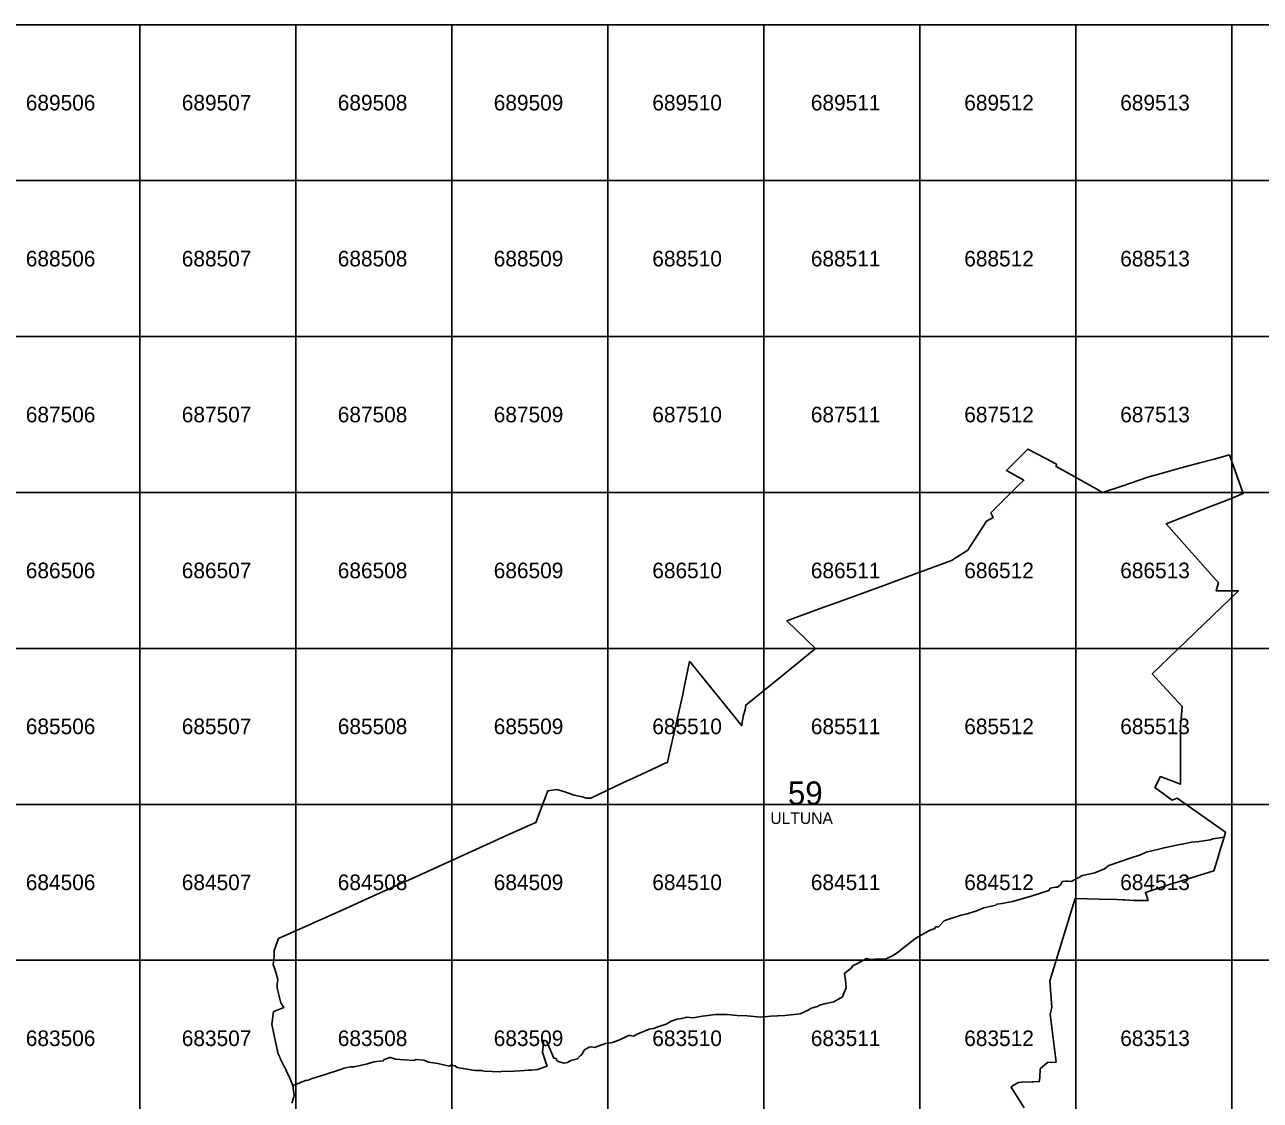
# Model space of a CAD drawing. Extents: x 25485000 to 25520000, y 6656775 to 6690000.
# Drawn here: x 25506262 to 25514183, y 6683102 to 6690000 of the extents above; entities that cross this region are included whole.
import ezdxf

# ---------------------------------------------------------------- set-up
doc = ezdxf.new("R2010")
doc.units = 0
doc.layers.add('Level 63', color=7, linetype='Continuous')

msp = doc.modelspace()

# ---------------------------------------------------------------- linework, layer by layer
at = {"layer": 'Level 63'}
for points in [[(25506000, 6689000), (25507000, 6689000), (25507000, 6690000), (25506000, 6690000)], [(25507000, 6689000), (25508000, 6689000), (25508000, 6690000), (25507000, 6690000)], [(25508000, 6689000), (25509000, 6689000), (25509000, 6690000), (25508000, 6690000)], [(25509000, 6689000), (25510000, 6689000), (25510000, 6690000), (25509000, 6690000)], [(25510000, 6689000), (25511000, 6689000), (25511000, 6690000), (25510000, 6690000)], [(25511000, 6689000), (25512000, 6689000), (25512000, 6690000), (25511000, 6690000)], [(25512000, 6689000), (25513000, 6689000), (25513000, 6690000), (25512000, 6690000)], [(25513000, 6689000), (25514000, 6689000), (25514000, 6690000), (25513000, 6690000)], [(25514000, 6689000), (25515000, 6689000), (25515000, 6690000), (25514000, 6690000)], [(25506000, 6688000), (25507000, 6688000), (25507000, 6689000), (25506000, 6689000)], [(25507000, 6688000), (25508000, 6688000), (25508000, 6689000), (25507000, 6689000)], [(25508000, 6688000), (25509000, 6688000), (25509000, 6689000), (25508000, 6689000)], [(25509000, 6688000), (25510000, 6688000), (25510000, 6689000), (25509000, 6689000)], [(25510000, 6688000), (25511000, 6688000), (25511000, 6689000), (25510000, 6689000)], [(25511000, 6688000), (25512000, 6688000), (25512000, 6689000), (25511000, 6689000)], [(25512000, 6688000), (25513000, 6688000), (25513000, 6689000), (25512000, 6689000)], [(25513000, 6688000), (25514000, 6688000), (25514000, 6689000), (25513000, 6689000)], [(25514000, 6688000), (25515000, 6688000), (25515000, 6689000), (25514000, 6689000)], [(25506000, 6687000), (25507000, 6687000), (25507000, 6688000), (25506000, 6688000)], [(25507000, 6687000), (25508000, 6687000), (25508000, 6688000), (25507000, 6688000)], [(25508000, 6687000), (25509000, 6687000), (25509000, 6688000), (25508000, 6688000)], [(25509000, 6687000), (25510000, 6687000), (25510000, 6688000), (25509000, 6688000)], [(25510000, 6687000), (25511000, 6687000), (25511000, 6688000), (25510000, 6688000)], [(25511000, 6687000), (25512000, 6687000), (25512000, 6688000), (25511000, 6688000)], [(25512000, 6687000), (25513000, 6687000), (25513000, 6688000), (25512000, 6688000)], [(25513000, 6687000), (25514000, 6687000), (25514000, 6688000), (25513000, 6688000)], [(25514000, 6687000), (25515000, 6687000), (25515000, 6688000), (25514000, 6688000)], [(25507847.3, 6683582.4), (25507847.8, 6683580), (25507869.5, 6683475.9), (25507881.4, 6683418.8), (25507882, 6683416.3), (25507882.2, 6683415.6), (25507883.4, 6683411.3), (25507883.5, 6683411), (25507885.2, 6683405.4), (25507886.6, 6683401.2), (25507889, 6683394.1), (25507890, 6683392), (25507895.7, 6683384.5), (25507897.7, 6683376.6), (25507899.4, 6683372.8), (25507900.8, 6683369.4), (25507902.2, 6683366.1), (25507903.7, 6683362.5), (25507905.7, 6683357.8), (25507910, 6683347.6), (25507915.8, 6683336.1), (25507924.8, 6683319.1), (25507930.5, 6683307.5), (25507934.9, 6683298.6), (25507940.6, 6683286.9), (25507949.9, 6683268.2), (25507967.5, 6683229), (25507975.8, 6683208.3), (25507979.5, 6683195.8), (25507984.3, 6683197.2), (25508065.8, 6683230), (25508073.3, 6683229.8), (25508103.9, 6683242.5), (25508180.9, 6683266.1), (25508287.1, 6683299.7), (25508309.5, 6683308), (25508349.1, 6683316.9), (25508373.2, 6683315.9), (25508458.2, 6683335.5), (25508460.1, 6683335.9), (25508501.3, 6683349), (25508517.7, 6683350.9), (25508560.2, 6683354), (25508565, 6683364.6), (25508603, 6683375.9), (25508606.4, 6683376.9), (25508638, 6683365.9), (25508755.1, 6683358), (25508772, 6683363.4), (25508819.6, 6683358.6), (25508851.2, 6683346.3), (25508910.4, 6683337), (25508983.1, 6683321.2), (25508995.7, 6683327.7), (25509020.3, 6683323.5), (25509034.8, 6683312.7), (25509150.2, 6683292.8), (25509189.6, 6683293.6), (25509207.4, 6683287.8), (25509305.6, 6683283.5), (25509327.6, 6683289.6), (25509366.6, 6683287.6), (25509466.4, 6683293.7), (25509487.9, 6683295), (25509513.6, 6683295.5), (25509549.1, 6683300.5), (25509610.1, 6683319.9), (25509600.7, 6683349.8), (25509580.5, 6683411.1), (25509590.6, 6683486.9), (25509606.7, 6683483.2), (25509653.4, 6683371.6), (25509668, 6683370.5), (25509673.7, 6683357.5), (25509687.4, 6683347.6), (25509720.6, 6683340.8), (25509741.5, 6683345), (25509762.9, 6683357.9), (25509806.6, 6683366.8), (25509823.5, 6683386.5), (25509832.3, 6683396.1), (25509848.6, 6683422.7), (25509851, 6683426.6), (25509880.1, 6683442.2), (25509894.7, 6683445.5), (25509916.7, 6683441.2), (25509941.5, 6683451), (25509955.2, 6683454.6), (25509984.6, 6683465.8), (25510030.7, 6683471.7), (25510082.1, 6683491.8), (25510133.3, 6683518.3), (25510143.6, 6683517.4), (25510164.4, 6683514.2), (25510184.4, 6683524.2), (25510202.1, 6683532.1), (25510265.1, 6683558.7), (25510293, 6683561.4), (25510326.2, 6683576.1), (25510373.7, 6683589.2), (25510406.4, 6683609.6), (25510444, 6683622.6), (25510471.5, 6683626.8), (25510481.2, 6683628.2), (25510505.5, 6683636.1), (25510546.8, 6683630.7), (25510606.8, 6683641.6), (25510689.7, 6683651.7), (25510764.6, 6683652.6), (25510828.2, 6683645.5), (25510894.2, 6683642.9), (25510981.1, 6683636.1), (25511044.2, 6683640.9), (25511134.6, 6683645.8), (25511233.3, 6683656.8), (25511284.7, 6683679.2), (25511304.1, 6683693.8), (25511343.4, 6683702.5), (25511357.1, 6683713.1), (25511396.9, 6683723.8), (25511448.8, 6683734.2), (25511504, 6683765.6), (25511513.2, 6683789), (25511527.1, 6683822.7), (25511523.5, 6683872.2), (25511517, 6683915.9), (25511542, 6683936.2), (25511562.4, 6683951.3), (25511569.2, 6683963.2), (25511569, 6683963.7), (25511592.9, 6683974.4), (25511658.2, 6684010.3), (25511686.7, 6684005.2), (25511731.5, 6684009), (25511777.5, 6684007.9), (25511821.6, 6684025.4), (25511854.5, 6684048.2), (25511957.6, 6684129.6), (25511979.4, 6684142.9), (25512053.1, 6684187.2), (25512069.8, 6684195), (25512079.8, 6684197.3), (25512095.8, 6684204.1), (25512101, 6684214.1), (25512119.9, 6684214.9), (25512157.3, 6684253), (25512167.3, 6684256.3), (25512264.3, 6684288.6), (25512294.8, 6684296.4), (25512359.1, 6684314.4), (25512410.8, 6684337.2), (25512487.2, 6684352.8), (25512493.1, 6684360.4), (25512527, 6684363.9), (25512594, 6684376.7), (25512708.6, 6684408.2), (25512827.1, 6684446.4), (25512836.4, 6684461.4), (25512869.1, 6684468), (25512883.3, 6684469.3), (25512901.4, 6684484.6), (25512913.5, 6684505.6), (25512934.3, 6684506.8), (25512951.5, 6684507.9), (25512970.1, 6684504.8), (25513043.6, 6684544.3), (25513122.5, 6684561), (25513183.3, 6684586.9), (25513212.6, 6684608), (25513348.2, 6684655.2), (25513414.4, 6684675.7), (25513451.6, 6684694.1), (25513525, 6684710.5), (25513566.1, 6684721.4), (25513678.5, 6684743.7), (25513682.5, 6684744.3), (25513742.5, 6684757.4), (25513791.7, 6684762.6), (25513864.4, 6684773.3), (25513878.2, 6684778.6), (25513950.8, 6684790.5), (25513960.6, 6684822.1), (25513650, 6685040.2), (25513618.5, 6685027.3), (25513507.8, 6685109), (25513543.8, 6685178.3), (25513671.2, 6685128.7), (25513672, 6685443.4), (25513671.5, 6685497.9), (25513682.8, 6685627.1), (25513607.5, 6685709.5), (25513490.5, 6685837.9), (25513540.7, 6685886.7), (25513598.7, 6685941.9), (25514043, 6686369), (25513899.4, 6686369.8), (25513914.4, 6686422.5), (25513898.8, 6686440.1), (25513712.5, 6686650.3), (25513580.5, 6686799.5), (25513864.7, 6686910.4), (25513980.9, 6686955.7), (25514074.2, 6686992.5), (25513984.6, 6687240.9), (25513888.3, 6687214.7), (25513795.6, 6687189.6), (25513644.1, 6687148.7), (25513532.3, 6687117.7), (25513462.9, 6687097.4), (25513295.5, 6687041.1), (25513171.7, 6687000.9), (25513135.4, 6687021.1), (25512974.3, 6687111.2), (25512873.4, 6687165.9), (25512875.7, 6687181.6), (25512808, 6687217.3), (25512692, 6687278.6), (25512555.6, 6687141.9), (25512667.9, 6687079), (25512635.5, 6687048.2), (25512454.7, 6686870.3), (25512471.3, 6686839), (25512428.5, 6686816.6), (25512308.8, 6686630.8), (25512203.8, 6686562.9), (25511838.9, 6686428.2), (25511775, 6686405), (25511463.5, 6686292.6), (25511361, 6686255.2), (25511148.2, 6686177.6), (25511331.8, 6685998.4), (25511178.3, 6685874.2), (25511029.7, 6685754.2), (25510883.7, 6685636.4), (25510880.7, 6685605.8), (25510870.2, 6685570.9), (25510860.9, 6685527.1), (25510859.1, 6685503.6), (25510839.5, 6685528), (25510816.6, 6685556.7), (25510632.7, 6685783.7), (25510525.6, 6685915.5), (25510524.3, 6685917), (25510488, 6685741), (25510479.9, 6685705.3), (25510391.3, 6685311), (25510387.7, 6685288.3), (25510382.7, 6685270.4), (25510185, 6685178.4), (25510096.1, 6685137.1), (25510047.7, 6685114.2), (25509890.9, 6685039.3), (25509863, 6685039.8), (25509835.1, 6685047.9), (25509785, 6685058.4), (25509718.7, 6685081.7), (25509673.5, 6685095.5), (25509615.5, 6685087.4), (25509538.8, 6684883.7), (25509490.1, 6684862.3), (25509369.8, 6684807.7), (25508816, 6684557), (25508660.2, 6684486.4), (25508517.5, 6684421.2), (25508300.5, 6684323.4), (25507888.6, 6684138.6), (25507860.6, 6684062.7), (25507860, 6684023.6), (25507854.7, 6683973), (25507865, 6683943.5), (25507874.2, 6683915.4), (25507884, 6683876.5), (25507879, 6683847.7), (25507880.9, 6683821.2), (25507882.9, 6683813), (25507904.6, 6683727.9), (25507922.3, 6683697), (25507858.3, 6683671.6), (25507856.8, 6683671), (25507846, 6683589.2), (25507846.8, 6683585.3)], [(25506000, 6686000), (25507000, 6686000), (25507000, 6687000), (25506000, 6687000)], [(25507000, 6686000), (25508000, 6686000), (25508000, 6687000), (25507000, 6687000)], [(25508000, 6686000), (25509000, 6686000), (25509000, 6687000), (25508000, 6687000)], [(25509000, 6686000), (25510000, 6686000), (25510000, 6687000), (25509000, 6687000)], [(25510000, 6686000), (25511000, 6686000), (25511000, 6687000), (25510000, 6687000)], [(25511000, 6686000), (25512000, 6686000), (25512000, 6687000), (25511000, 6687000)], [(25512000, 6686000), (25513000, 6686000), (25513000, 6687000), (25512000, 6687000)], [(25513000, 6686000), (25514000, 6686000), (25514000, 6687000), (25513000, 6687000)], [(25514000, 6686000), (25515000, 6686000), (25515000, 6687000), (25514000, 6687000)], [(25506000, 6685000), (25507000, 6685000), (25507000, 6686000), (25506000, 6686000)], [(25507000, 6685000), (25508000, 6685000), (25508000, 6686000), (25507000, 6686000)], [(25508000, 6685000), (25509000, 6685000), (25509000, 6686000), (25508000, 6686000)], [(25509000, 6685000), (25510000, 6685000), (25510000, 6686000), (25509000, 6686000)], [(25510000, 6685000), (25511000, 6685000), (25511000, 6686000), (25510000, 6686000)], [(25511000, 6685000), (25512000, 6685000), (25512000, 6686000), (25511000, 6686000)], [(25512000, 6685000), (25513000, 6685000), (25513000, 6686000), (25512000, 6686000)], [(25513000, 6685000), (25514000, 6685000), (25514000, 6686000), (25513000, 6686000)], [(25514000, 6685000), (25515000, 6685000), (25515000, 6686000), (25514000, 6686000)], [(25506000, 6684000), (25507000, 6684000), (25507000, 6685000), (25506000, 6685000)], [(25507000, 6684000), (25508000, 6684000), (25508000, 6685000), (25507000, 6685000)], [(25508000, 6684000), (25509000, 6684000), (25509000, 6685000), (25508000, 6685000)], [(25509000, 6684000), (25510000, 6684000), (25510000, 6685000), (25509000, 6685000)], [(25510000, 6684000), (25511000, 6684000), (25511000, 6685000), (25510000, 6685000)], [(25511000, 6684000), (25512000, 6684000), (25512000, 6685000), (25511000, 6685000)], [(25512000, 6684000), (25513000, 6684000), (25513000, 6685000), (25512000, 6685000)], [(25513000, 6684000), (25514000, 6684000), (25514000, 6685000), (25513000, 6685000)], [(25514000, 6684000), (25515000, 6684000), (25515000, 6685000), (25514000, 6685000)], [(25506000, 6683000), (25507000, 6683000), (25507000, 6684000), (25506000, 6684000)], [(25507000, 6683000), (25508000, 6683000), (25508000, 6684000), (25507000, 6684000)], [(25508000, 6683000), (25509000, 6683000), (25509000, 6684000), (25508000, 6684000)], [(25509000, 6683000), (25510000, 6683000), (25510000, 6684000), (25509000, 6684000)], [(25510000, 6683000), (25511000, 6683000), (25511000, 6684000), (25510000, 6684000)], [(25511000, 6683000), (25512000, 6683000), (25512000, 6684000), (25511000, 6684000)], [(25512000, 6683000), (25513000, 6683000), (25513000, 6684000), (25512000, 6684000)], [(25513000, 6683000), (25514000, 6683000), (25514000, 6684000), (25513000, 6684000)], [(25514000, 6683000), (25515000, 6683000), (25515000, 6684000), (25514000, 6684000)]]:
    msp.add_lwpolyline(points, close=True, dxfattribs=at)
msp.add_lwpolyline([(25512669.9, 6683054), (25512585.5, 6683185.2), (25512601.4, 6683199.5), (25512633.5, 6683216.4), (25512653.6, 6683217.6), (25512720.7, 6683220.1), (25512729.3, 6683220.3), (25512745.6, 6683222.3), (25512766.4, 6683221), (25512768.8, 6683251.3), (25512771, 6683303.1), (25512819.4, 6683343.3), (25512873.9, 6683347.3), (25512835.5, 6683654.2), (25512845.9, 6683697.7), (25512834.3, 6683869.1), (25512976.3, 6684333.6), (25512996.7, 6684396.5), (25513149.6, 6684392.6), (25513262.6, 6684389.4), (25513298.9, 6684388.4), (25513315.1, 6684387.3), (25513371.3, 6684383.7), (25513463.3, 6684384.2), (25513447, 6684435.5), (25513595.5, 6684482.8), (25513884.7, 6684573.2), (25513908.2, 6684649), (25513930.6, 6684723.8), (25513931.6, 6684726.6), (25513950.8, 6684790.5), (25513878.2, 6684778.6), (25513864.4, 6684773.3), (25513791.7, 6684762.6), (25513742.5, 6684757.4), (25513682.5, 6684744.3), (25513678.5, 6684743.7), (25513566.1, 6684721.4), (25513525, 6684710.5), (25513451.6, 6684694.1), (25513414.4, 6684675.7), (25513348.2, 6684655.2), (25513212.6, 6684608), (25513183.3, 6684586.9), (25513122.5, 6684561), (25513043.6, 6684544.3), (25512970.1, 6684504.8), (25512951.5, 6684507.9), (25512934.3, 6684506.8), (25512913.5, 6684505.6), (25512901.4, 6684484.6), (25512883.3, 6684469.3), (25512869.1, 6684468), (25512836.4, 6684461.4), (25512827.1, 6684446.4), (25512708.6, 6684408.2), (25512594, 6684376.7), (25512527, 6684363.9), (25512493.1, 6684360.4), (25512487.2, 6684352.8), (25512410.8, 6684337.2), (25512359.1, 6684314.4), (25512294.8, 6684296.4), (25512264.3, 6684288.6), (25512167.3, 6684256.3), (25512157.3, 6684253), (25512119.9, 6684214.9), (25512101, 6684214.1), (25512095.8, 6684204.1), (25512079.8, 6684197.3), (25512069.8, 6684195), (25512053.1, 6684187.2), (25511979.4, 6684142.9), (25511957.6, 6684129.6), (25511854.5, 6684048.2), (25511821.6, 6684025.4), (25511777.5, 6684007.9), (25511731.5, 6684009), (25511686.7, 6684005.2), (25511658.2, 6684010.3), (25511592.9, 6683974.4), (25511569, 6683963.7), (25511569.2, 6683963.2), (25511562.4, 6683951.3), (25511542, 6683936.2), (25511517, 6683915.9), (25511523.5, 6683872.2), (25511527.1, 6683822.7), (25511513.2, 6683789), (25511504, 6683765.6), (25511448.8, 6683734.2), (25511396.9, 6683723.8), (25511357.1, 6683713.1), (25511343.4, 6683702.5), (25511304.1, 6683693.8), (25511284.7, 6683679.2), (25511233.3, 6683656.8), (25511134.6, 6683645.8), (25511044.2, 6683640.9), (25510981.1, 6683636.1), (25510894.2, 6683642.9), (25510828.2, 6683645.5), (25510764.6, 6683652.6), (25510689.7, 6683651.7), (25510606.8, 6683641.6), (25510546.8, 6683630.7), (25510505.5, 6683636.1), (25510481.2, 6683628.2), (25510471.5, 6683626.8), (25510444, 6683622.6), (25510406.4, 6683609.6), (25510373.7, 6683589.2), (25510326.2, 6683576.1), (25510293, 6683561.4), (25510265.1, 6683558.7), (25510202.1, 6683532.1), (25510184.4, 6683524.2), (25510164.4, 6683514.2), (25510143.6, 6683517.4), (25510133.3, 6683518.3), (25510082.1, 6683491.8), (25510030.7, 6683471.7), (25509984.6, 6683465.8), (25509955.2, 6683454.6), (25509941.5, 6683451), (25509916.7, 6683441.2), (25509894.7, 6683445.5), (25509880.1, 6683442.2), (25509851, 6683426.6), (25509848.6, 6683422.7), (25509832.3, 6683396.1), (25509823.5, 6683386.5), (25509806.6, 6683366.8), (25509762.9, 6683357.9), (25509741.5, 6683345), (25509720.6, 6683340.8), (25509687.4, 6683347.6), (25509673.7, 6683357.5), (25509668, 6683370.5), (25509653.4, 6683371.6), (25509606.7, 6683483.2), (25509590.6, 6683486.9), (25509580.5, 6683411.1), (25509600.7, 6683349.8), (25509610.1, 6683319.9), (25509549.1, 6683300.5), (25509513.6, 6683295.5), (25509487.9, 6683295), (25509466.4, 6683293.7), (25509366.6, 6683287.6), (25509327.6, 6683289.6), (25509305.6, 6683283.5), (25509207.4, 6683287.8), (25509189.6, 6683293.6), (25509150.2, 6683292.8), (25509034.8, 6683312.7), (25509020.3, 6683323.5), (25508995.7, 6683327.7), (25508983.1, 6683321.2), (25508910.4, 6683337), (25508851.2, 6683346.3), (25508819.6, 6683358.6), (25508772, 6683363.4), (25508755.1, 6683358), (25508638, 6683365.9), (25508606.4, 6683376.9), (25508603, 6683375.9), (25508565, 6683364.6), (25508560.2, 6683354), (25508517.7, 6683350.9), (25508501.3, 6683349), (25508460.1, 6683335.9), (25508458.2, 6683335.5), (25508373.2, 6683315.9), (25508349.1, 6683316.9), (25508309.5, 6683308), (25508287.1, 6683299.7), (25508180.9, 6683266.1), (25508103.9, 6683242.5), (25508073.3, 6683229.8), (25508065.8, 6683230), (25507984.3, 6683197.2), (25507979.5, 6683195.8), (25507989.8, 6683132.8), (25507986.9, 6683124.1), (25507973.1, 6683082.6)], dxfattribs=at)

# ---------------------------------------------------------------- texts
for s, height, p in [('689506', 100, (25506268.5, 6689450)), ('689507', 100, (25507268.5, 6689450)), ('689508', 100, (25508268.5, 6689450)), ('689509', 100, (25509268.5, 6689450)), ('689510', 100, (25510285.1, 6689450)), ('689511', 100, (25511301.6, 6689450)), ('689512', 100, (25512285.1, 6689450)), ('689513', 100, (25513285.1, 6689450)), ('688506', 100, (25506268.5, 6688450)), ('688507', 100, (25507268.5, 6688450)), ('688508', 100, (25508268.5, 6688450)), ('688509', 100, (25509268.5, 6688450)), ('688510', 100, (25510285.1, 6688450)), ('688511', 100, (25511301.6, 6688450)), ('688512', 100, (25512285.1, 6688450)), ('688513', 100, (25513285.1, 6688450)), ('687506', 100, (25506268.5, 6687450)), ('687507', 100, (25507268.5, 6687450)), ('687508', 100, (25508268.5, 6687450)), ('687509', 100, (25509268.5, 6687450)), ('687510', 100, (25510285.1, 6687450)), ('687511', 100, (25511301.6, 6687450)), ('687512', 100, (25512285.1, 6687450)), ('687513', 100, (25513285.1, 6687450)), ('686506', 100, (25506268.5, 6686450)), ('686507', 100, (25507268.5, 6686450)), ('686508', 100, (25508268.5, 6686450)), ('686509', 100, (25509268.5, 6686450)), ('686510', 100, (25510285.1, 6686450)), ('686511', 100, (25511301.6, 6686450)), ('686512', 100, (25512285.1, 6686450)), ('686513', 100, (25513285.1, 6686450)), ('685506', 100, (25506268.5, 6685450)), ('685507', 100, (25507268.5, 6685450)), ('685508', 100, (25508268.5, 6685450)), ('685509', 100, (25509268.5, 6685450)), ('685510', 100, (25510285.1, 6685450)), ('685511', 100, (25511301.6, 6685450)), ('685512', 100, (25512285.1, 6685450)), ('685513', 100, (25513285.1, 6685450)), ('59', 150, (25511154.3, 6684996.8)), ('ULTUNA', 75, (25511041.8, 6684873.9)), ('684506', 100, (25506268.5, 6684450)), ('684507', 100, (25507268.5, 6684450)), ('684508', 100, (25508268.5, 6684450)), ('684509', 100, (25509268.5, 6684450)), ('684510', 100, (25510285.1, 6684450)), ('684511', 100, (25511301.6, 6684450)), ('684512', 100, (25512285.1, 6684450)), ('684513', 100, (25513285.1, 6684450)), ('683506', 100, (25506268.5, 6683450)), ('683507', 100, (25507268.5, 6683450)), ('683508', 100, (25508268.5, 6683450)), ('683509', 100, (25509268.5, 6683450)), ('683510', 100, (25510285.1, 6683450)), ('683511', 100, (25511301.6, 6683450)), ('683512', 100, (25512285.1, 6683450)), ('683513', 100, (25513285.1, 6683450))]:
    msp.add_text(s, height=height, dxfattribs=at).set_placement(p)

doc.saveas('drawing.dxf')
